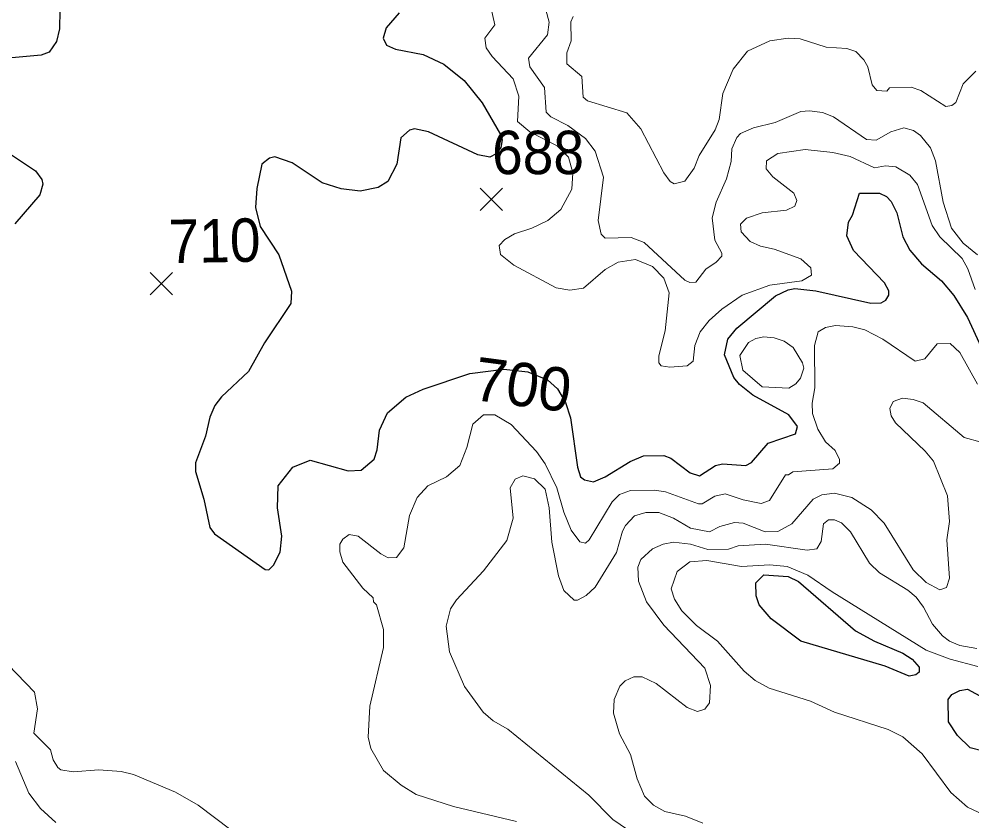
# Model space of a CAD drawing. Extents: x 265 to 291.4, y 7731.5 to 7759.6.
# Drawn here: x 267.199 to 268.956, y 7756.199 to 7757.677 of the extents above; entities that cross this region are included whole.
import ezdxf
from ezdxf.enums import TextEntityAlignment as Align

# ---------------------------------------------------------------- set-up
doc = ezdxf.new("R2010")
doc.units = 0
doc.header["$LTSCALE"] = 0.032
for name, color, linetype, lineweight in [('1', 7, 'Continuous', 25), ('2', 7, 'Continuous', 13), ('21', 7, 'Continuous', 25), ('61', 7, 'Continuous', 13)]:
    doc.layers.add(name, color=color, linetype=linetype, lineweight=lineweight)

msp = doc.modelspace()

# ---------------------------------------------------------------- linework, layer by layer
at = {"layer": '1'}
for points in [[(267.2742, 7757.7282), (267.2734, 7757.659), (267.2678, 7757.6352), (267.2543, 7757.6161), (267.2392, 7757.6105), (267.1787, 7757.6049)], [(267.8994, 7757.6884), (267.8755, 7757.6606), (267.87, 7757.6415), (267.8764, 7757.6288), (267.8931, 7757.6216), (267.944, 7757.6113), (267.9822, 7757.5938), (268.0196, 7757.5636), (268.0529, 7757.5222), (268.0864, 7757.4641), (268.0894, 7757.4542), (268.0874, 7757.4403), (268.0788, 7757.4284), (268.0669, 7757.4224), (268.045, 7757.4264), (267.9535, 7757.4689), (267.928, 7757.4745), (267.9185, 7757.4721), (267.9026, 7757.4578), (267.8954, 7757.4093), (267.8787, 7757.3774), (267.8612, 7757.3663), (267.8278, 7757.3599), (267.7928, 7757.3639), (267.7578, 7757.375), (267.7022, 7757.4116), (267.6703, 7757.4228), (267.6608, 7757.4204), (267.6464, 7757.4093)], [(267.1509, 7757.449), (267.2288, 7757.3973), (267.2408, 7757.3814), (267.2424, 7757.3727), (267.2368, 7757.3528), (267.1906, 7757.2995)], [(267.6464, 7757.4093), (267.6369, 7757.3647), (267.6345, 7757.3297), (267.6433, 7757.2947), (267.6775, 7757.2422), (267.7013, 7757.1754), (267.6997, 7757.1523)], [(267.6997, 7757.1523), (267.6512, 7757.0799), (267.6218, 7757.0274), (267.5717, 7756.9805), (267.5597, 7756.9646), (267.5502, 7756.9431), (267.5422, 7756.9081), (267.5239, 7756.8588), (267.5239, 7756.8429), (267.5391, 7756.792), (267.5502, 7756.7395), (267.5589, 7756.7283), (267.6528, 7756.6623), (267.6592, 7756.6615), (267.6679, 7756.6702), (267.6799, 7756.6941), (267.683, 7756.7235), (267.6751, 7756.7761), (267.6767, 7756.8166), (267.7038, 7756.8508), (267.7356, 7756.8635), (267.8056, 7756.8444), (267.8294, 7756.8452), (267.8533, 7756.8659), (267.8588, 7756.8826), (267.8636, 7756.9192), (267.8779, 7756.9511), (267.9122, 7756.9797), (267.944, 7756.9948), (268.0299, 7757.0234), (268.093, 7757.0313), (268.1368, 7757.0266), (268.1732, 7757.0121), (268.1917, 7756.9955), (268.2063, 7756.9703), (268.2156, 7756.9418), (268.2287, 7756.8508), (268.2343, 7756.8333), (268.2415, 7756.8277), (268.2582, 7756.8238), (268.2797, 7756.8333), (268.3258, 7756.8611), (268.3505, 7756.8715), (268.3879, 7756.8723), (268.4006, 7756.8675), (268.4364, 7756.8405), (268.4539, 7756.8349), (268.4833, 7756.854), (268.4961, 7756.8572), (268.539, 7756.854), (268.5493, 7756.8595), (268.5804, 7756.8953), (268.6305, 7756.9121), (268.6344, 7756.9256), (268.6185, 7756.9471), (268.5517, 7756.9837), (268.5271, 7757.0035), (268.5167, 7757.0163), (268.5, 7757.0577), (268.5056, 7757.0871), (268.5223, 7757.107), (268.5939, 7757.1666), (268.617, 7757.1777), (268.6297, 7757.1801), (268.6679, 7757.1762), (268.7697, 7757.1531), (268.7888, 7757.1539), (268.7975, 7757.1587), (268.8031, 7757.1682), (268.8031, 7757.1762), (268.7951, 7757.1905), (268.7379, 7757.2501), (268.7251, 7757.2772), (268.7283, 7757.3027), (268.7355, 7757.3154), (268.749, 7757.3559), (268.7856, 7757.3559), (268.7983, 7757.3496), (268.8071, 7757.3408), (268.8174, 7757.3194), (268.8285, 7757.2756), (268.8413, 7757.251), (268.8628, 7757.2255), (268.9001, 7757.1945), (268.9224, 7757.1674), (268.9479, 7757.1269), (268.9733, 7757.072)]]:
    msp.add_lwpolyline(points, dxfattribs=at)
for points in [[(268.6408, 7756.5302), (268.5859, 7756.5716), (268.5636, 7756.5971), (268.5581, 7756.6138), (268.5573, 7756.6376), (268.5724, 7756.6527), (268.617, 7756.6495), (268.6361, 7756.64), (268.7411, 7756.5493), (268.7761, 7756.5302), (268.8286, 7756.5079), (268.8461, 7756.4968), (268.8588, 7756.4825), (268.8588, 7756.473), (268.8524, 7756.4682), (268.8405, 7756.4658), (268.7959, 7756.4841)], [(268.9121, 7756.4228), (268.9192, 7756.4316), (268.9336, 7756.4395), (268.9479, 7756.4419), (268.9773, 7756.426), (269.0052, 7756.399), (269.0274, 7756.368), (269.0163, 7756.3353), (269.0067, 7756.329), (268.9765, 7756.3274), (268.9526, 7756.3337), (268.9296, 7756.356), (268.9129, 7756.3815)]]:
    msp.add_lwpolyline(points, close=True, dxfattribs=at)
at = {"layer": '2'}
for points in [[(268.0665, 7757.71), (268.076, 7757.6662), (268.0577, 7757.6415), (268.0601, 7757.624), (268.0712, 7757.6081), (268.1102, 7757.5668), (268.1206, 7757.5349), (268.1182, 7757.488), (268.1405, 7757.4689), (268.1909, 7757.4434), (268.2121, 7757.4221), (268.22, 7757.3936), (268.2184, 7757.3631), (268.1977, 7757.3257), (268.1739, 7757.3058), (268.1444, 7757.2915), (268.1126, 7757.2812), (268.0943, 7757.2708), (268.084, 7757.2597), (268.0864, 7757.243), (268.111, 7757.2231), (268.189, 7757.1817), (268.2145, 7757.177)], [(268.9662, 7757.2422), (268.9399, 7757.2637), (268.9184, 7757.2915), (268.9033, 7757.3393), (268.889, 7757.4156), (268.8795, 7757.4395), (268.8612, 7757.4625), (268.8484, 7757.4713), (268.8302, 7757.4761), (268.8063, 7757.4689), (268.7792, 7757.4538), (268.7617, 7757.4546), (268.7005, 7757.4968), (268.6806, 7757.5047), (268.6567, 7757.5079), (268.6408, 7757.5063), (268.5931, 7757.4864), (268.5533, 7757.4761), (268.5295, 7757.4657), (268.5223, 7757.4586), (268.5135, 7757.4379), (268.512, 7757.414), (268.5032, 7757.3822), (268.4841, 7757.3393), (268.477, 7757.3106), (268.4817, 7757.2693), (268.4945, 7757.2454), (268.4945, 7757.2398), (268.4841, 7757.2287), (268.465, 7757.2159), (268.4467, 7757.1921), (268.4356, 7757.1913), (268.4268, 7757.1953), (268.3513, 7757.2653), (268.3274, 7757.274), (268.2797, 7757.2732), (268.2725, 7757.2804), (268.2669, 7757.3058), (268.2765, 7757.3854), (268.2614, 7757.4331), (268.2431, 7757.457), (268.2105, 7757.4808), (268.1795, 7757.4968), (268.1707, 7757.5055), (268.1675, 7757.5509), (268.1405, 7757.589), (268.1381, 7757.6049), (268.1731, 7757.6479), (268.1763, 7757.671), (268.1699, 7757.694)], [(268.2208, 7757.6813), (268.216, 7757.6717), (268.2168, 7757.6368), (268.2089, 7757.6145), (268.2089, 7757.5946), (268.2367, 7757.5707), (268.2391, 7757.5326), (268.2471, 7757.5262), (268.3194, 7757.5039), (268.3457, 7757.4745), (268.3879, 7757.3933)], [(268.4825, 7757.4729), (268.4897, 7757.492), (268.4968, 7757.5397), (268.5159, 7757.5843), (268.5422, 7757.6177), (268.5836, 7757.6368), (268.617, 7757.6415), (268.6392, 7757.6407), (268.687, 7757.6248), (268.7252, 7757.6224), (268.7419, 7757.6169), (268.757, 7757.6017), (268.7641, 7757.589), (268.7721, 7757.5556), (268.7808, 7757.5453), (268.7991, 7757.5437), (268.8039, 7757.5501), (268.8437, 7757.5511), (268.862, 7757.5453), (268.9081, 7757.5158), (268.9193, 7757.5174), (268.9264, 7757.523), (268.9399, 7757.5572), (268.963, 7757.5811)], [(268.3879, 7757.3933), (268.3998, 7757.3774), (268.407, 7757.3734), (268.4268, 7757.3782), (268.4435, 7757.4021), (268.4531, 7757.4252), (268.4825, 7757.4729)], [(268.3879, 7757.1992), (268.3974, 7757.1722), (268.3902, 7757.1022), (268.3783, 7757.0561), (268.3783, 7757.0433), (268.3831, 7757.0378), (268.399, 7757.0354), (268.4308, 7757.0378), (268.442, 7757.0465), (268.4451, 7757.0752), (268.4547, 7757.1006), (268.4714, 7757.1213), (268.4945, 7757.142), (268.5326, 7757.1682), (268.5836, 7757.1865), (268.6424, 7757.1945), (268.6599, 7757.2048), (268.6591, 7757.2183), (268.6408, 7757.235), (268.5915, 7757.2525), (268.5661, 7757.2581), (268.547, 7757.2669), (268.5302, 7757.2844), (268.5295, 7757.2987), (268.5406, 7757.3098), (268.5692, 7757.3194), (268.6138, 7757.3249), (268.6297, 7757.3321), (268.6329, 7757.3424), (268.6273, 7757.3559), (268.5891, 7757.3862), (268.5764, 7757.4005), (268.5772, 7757.4156), (268.5979, 7757.4291), (268.6488, 7757.4363), (268.6997, 7757.4307), (268.7315, 7757.4236), (268.7761, 7757.4029), (268.7967, 7757.4061), (268.8158, 7757.4045), (268.8413, 7757.3894), (268.8556, 7757.3719), (268.8826, 7757.2963), (268.897, 7757.2756), (268.9383, 7757.2358), (268.9487, 7757.2167), (268.9622, 7757.1786)], [(268.2145, 7757.177), (268.2399, 7757.1809), (268.2797, 7757.2151), (268.3035, 7757.2287), (268.3354, 7757.2334), (268.3672, 7757.2207), (268.3879, 7757.1992)], [(268.5676, 7756.784), (268.5827, 7756.7896), (268.6122, 7756.8365), (268.6177, 7756.8365), (268.6257, 7756.8421), (268.6997, 7756.8476), (268.7116, 7756.858), (268.7116, 7756.8651), (268.7037, 7756.8818), (268.6862, 7756.8978), (268.6718, 7756.9208), (268.6623, 7756.9495), (268.6615, 7756.9686), (268.6663, 7756.9972), (268.6655, 7757.0752), (268.6726, 7757.1006), (268.6862, 7757.1086), (268.7045, 7757.1117), (268.7363, 7757.1093), (268.7586, 7757.1038), (268.792, 7757.0871), (268.8516, 7757.0465), (268.8691, 7757.0505), (268.8922, 7757.0783), (268.9161, 7757.0791), (268.9336, 7757.0624), (268.9662, 7757.0036)], [(268.9733, 7756.8969), (268.9415, 7756.9057), (268.8659, 7756.9693), (268.8477, 7756.9757), (268.8278, 7756.9781), (268.8111, 7756.9717), (268.8047, 7756.959), (268.8071, 7756.9455), (268.815, 7756.9328), (268.8699, 7756.8802), (268.885, 7756.862), (268.9113, 7756.7983), (268.9145, 7756.7506), (268.9097, 7756.7172), (268.9145, 7756.6464), (268.9089, 7756.6289), (268.897, 7756.6249), (268.8715, 7756.6384), (268.8476, 7756.6615), (268.7943, 7756.7474), (268.7705, 7756.7721), (268.7347, 7756.7951), (268.7029, 7756.8031), (268.679, 7756.7999), (268.6631, 7756.7919), (268.6241, 7756.7466), (268.5979, 7756.7323), (268.5748, 7756.7315), (268.5342, 7756.7474), (268.5183, 7756.749), (268.4913, 7756.7418), (268.4722, 7756.7315), (268.4372, 7756.7386), (268.4054, 7756.757), (268.3783, 7756.7673), (268.3545, 7756.7673), (268.3338, 7756.7609), (268.3171, 7756.7434), (268.3115, 7756.7331), (268.3004, 7756.6933), (268.2614, 7756.6297), (268.2447, 7756.6146), (268.2288, 7756.6058), (268.2224, 7756.6058), (268.2033, 7756.6233), (268.1938, 7756.6504), (268.181, 7756.7124), (268.1763, 7756.7761), (268.1691, 7756.8103), (268.1492, 7756.8293), (268.1277, 7756.8349), (268.1134, 7756.8285), (268.1047, 7756.8126), (268.1102, 7756.757), (268.0983, 7756.7156), (268.0553, 7756.6599), (268.0052, 7756.6066), (267.9941, 7756.5899), (267.9861, 7756.5581), (267.9925, 7756.5104), (268.0203, 7756.4467), (268.0545, 7756.399), (268.0728, 7756.3831), (268.0999, 7756.368), (268.2495, 7756.2462), (268.294, 7756.2017), (268.3767, 7756.1452)], [(268.1158, 7756.1977), (267.9997, 7756.2256), (267.9313, 7756.2478), (267.9034, 7756.2646), (267.8708, 7756.2916), (267.8477, 7756.3322), (267.8422, 7756.3529), (267.8453, 7756.4101), (267.8708, 7756.5183), (267.8708, 7756.5517), (267.8581, 7756.5971), (267.8525, 7756.6026), (267.8517, 7756.6098), (267.8326, 7756.6281), (267.796, 7756.6758), (267.7904, 7756.6949), (267.7904, 7756.7092), (267.796, 7756.718), (267.8072, 7756.7267), (267.8239, 7756.7235), (267.866, 7756.6909), (267.8795, 7756.6838), (267.8947, 7756.6846), (267.9082, 7756.7021), (267.9185, 7756.7617), (267.9328, 7756.7951), (267.9527, 7756.8166), (267.9869, 7756.8333), (268.0116, 7756.854), (268.0243, 7756.8874), (268.0355, 7756.9304), (268.0553, 7756.9471), (268.076, 7756.9471), (268.1063, 7756.9296), (268.1532, 7756.8795), (268.1691, 7756.8572), (268.1906, 7756.8126), (268.2033, 7756.7681), (268.2168, 7756.7347), (268.2327, 7756.7132), (268.2431, 7756.7108), (268.2502, 7756.7172), (268.2924, 7756.7872), (268.3059, 7756.8007), (268.3266, 7756.8079), (268.3704, 7756.8087), (268.391, 7756.8055)], [(268.391, 7756.8055), (268.4515, 7756.7832), (268.4587, 7756.7832), (268.4817, 7756.7975), (268.5008, 7756.8015), (268.5342, 7756.7904), (268.5676, 7756.784)], [(266.9751, 7756.7538), (266.9918, 7756.7386), (267.0029, 7756.7196), (267.0188, 7756.6488), (267.0387, 7756.6257), (267.0721, 7756.6241), (267.0952, 7756.6177), (267.1127, 7756.5971), (267.1461, 7756.5263), (267.1612, 7756.504), (267.2273, 7756.4364), (267.2328, 7756.4054), (267.2257, 7756.3608), (267.2567, 7756.3298), (267.2615, 7756.3115), (267.2702, 7756.2971), (267.2758, 7756.2932), (267.2981, 7756.2892), (267.3458, 7756.2932), (267.3871, 7756.29), (267.4094, 7756.2844), (267.4874, 7756.2518), (267.5287, 7756.2279), (267.6194, 7756.1595)], [(268.9654, 7756.5167), (268.9336, 7756.5223), (268.9145, 7756.5302), (268.9017, 7756.5398), (268.8834, 7756.5613), (268.8667, 7756.5931), (268.8532, 7756.6114), (268.8381, 7756.6241), (268.7856, 7756.6559), (268.7673, 7756.6742), (268.7323, 7756.7315), (268.7156, 7756.7482), (268.7029, 7756.7538), (268.6917, 7756.7538), (268.6822, 7756.7466), (268.6782, 7756.714), (268.6703, 7756.7005), (268.652, 7756.6981), (268.5756, 7756.7092), (268.5247, 7756.706), (268.5072, 7756.6997), (268.469, 7756.6989), (268.4372, 7756.7092), (268.4054, 7756.7124), (268.3863, 7756.7092)], [(268.3863, 7756.7092), (268.3672, 7756.7005), (268.3457, 7756.6806), (268.3401, 7756.6663), (268.3409, 7756.6408), (268.356, 7756.6026), (268.3879, 7756.5597)], [(268.5565, 7756.4578), (268.5358, 7756.4746), (268.4865, 7756.5302), (268.4483, 7756.5589), (268.4213, 7756.5859), (268.4077, 7756.6074), (268.4014, 7756.6265), (268.4125, 7756.6583), (268.4356, 7756.6766), (268.4674, 7756.679), (268.5311, 7756.6679), (268.5836, 7756.671), (268.6154, 7756.6679), (268.6536, 7756.6519), (268.6981, 7756.6209), (268.8715, 7756.5135), (268.9161, 7756.4968), (268.967, 7756.4833)], [(268.3879, 7756.5597), (268.4634, 7756.4801), (268.4738, 7756.4483), (268.4722, 7756.4165), (268.4634, 7756.4046), (268.4499, 7756.4006), (268.4308, 7756.4077), (268.3735, 7756.4523), (268.3481, 7756.4642), (268.3322, 7756.4642), (268.3163, 7756.457), (268.3067, 7756.4475), (268.2964, 7756.4229), (268.2948, 7756.3974), (268.3059, 7756.3592), (268.3266, 7756.321), (268.3385, 7756.2765), (268.3521, 7756.2447), (268.3688, 7756.228), (268.3895, 7756.216), (268.4276, 7756.2073), (268.4595, 7756.1945)], [(268.8643, 7756.3226), (268.8286, 7756.3536), (268.8015, 7756.3672), (268.7029, 7756.399), (268.6583, 7756.4197), (268.582, 7756.4435), (268.5565, 7756.4578)], [(268.9988, 7756.2001), (268.9479, 7756.224), (268.9169, 7756.251), (268.8643, 7756.3226)], [(267.2662, 7756.1961), (267.2384, 7756.2216), (267.2169, 7756.2502), (267.1922, 7756.3083)]]:
    msp.add_lwpolyline(points, dxfattribs=at)
msp.add_lwpolyline([(268.646, 7757.0333), (268.6433, 7757.0433), (268.6265, 7757.0712), (268.6098, 7757.0831), (268.5915, 7757.0895), (268.5724, 7757.091), (268.5573, 7757.0879), (268.5438, 7757.0807), (268.5279, 7757.0569), (268.5334, 7757.0298), (268.5692, 7756.9988), (268.6186, 7756.9964), (268.6313, 7757.0044), (268.64, 7757.0147)], close=True, dxfattribs=at)
at = {"layer": '21'}
for p, q in [((268.049, 7757.3653), (268.0902, 7757.3241)), ((268.0902, 7757.3653), (268.049, 7757.3241)), ((267.4407, 7757.2096), (267.4819, 7757.1684)), ((267.4819, 7757.2096), (267.4407, 7757.1684))]:
    msp.add_line(p, q, dxfattribs=at)

# ---------------------------------------------------------------- texts
at = {"layer": '61', "width": 0.95}
msp.add_text('688', height=0.08, dxfattribs=at).set_placement((268.1558, 7757.391), align=Align.CENTER)
msp.add_text('710', height=0.08, rotation=0.997, dxfattribs=at).set_placement((267.5598, 7757.2284), align=Align.CENTER)
at = {"layer": '61'}
msp.add_text('700', height=0.08, rotation=352.509, dxfattribs=at).set_placement((268.1226, 7756.9635), align=Align.CENTER)

doc.saveas('drawing.dxf')
